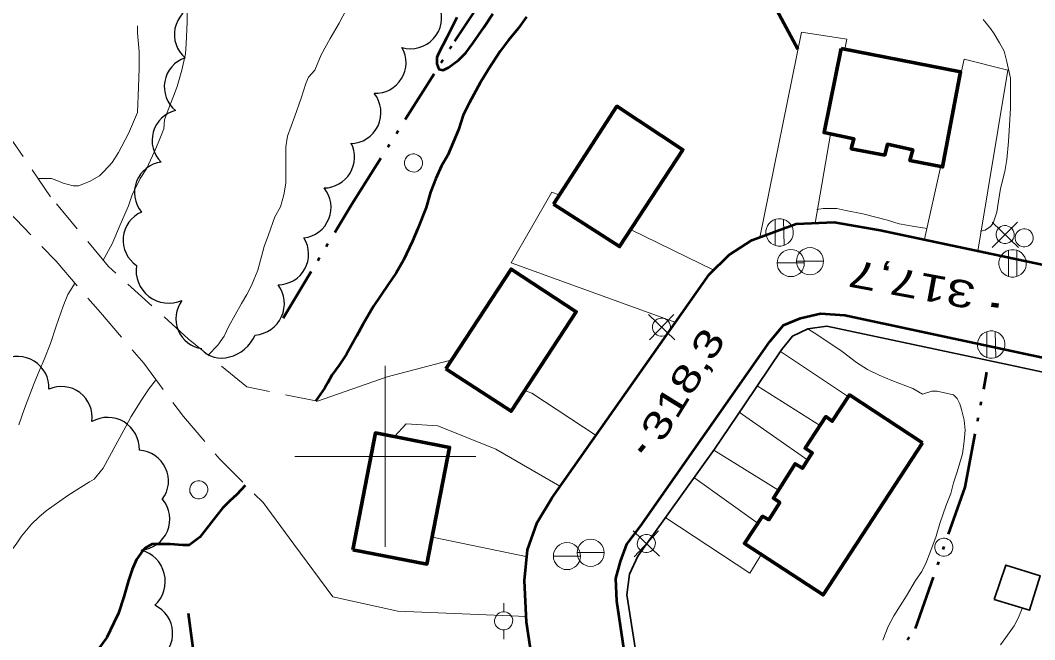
# Model space of a CAD drawing. Extents: x 240591 to 242335, y 5323482 to 5326937.
# Drawn here: x 241359.7 to 241471.8, y 5324579.8 to 5324648.2 of the extents above; entities that cross this region are included whole.
import ezdxf

# ---------------------------------------------------------------- set-up
doc = ezdxf.new("R2010")
doc.units = 0
doc.header["$LTSCALE"] = 1.2
for name, pattern in [('DASH_DOUBLE_DOT', [9.2, 5, -1.2, 0.3, -1.2, 0.3, -1.2]), ('LONG_DASHED', [7.5, 6, -1.5]), ('MEDIUM_DASHED', [4.5, 3, -1.5])]:
    doc.linetypes.add(name, pattern=pattern)
for name, color, linetype, lineweight in [('1', 7, 'Continuous', 53), ('19', 7, 'Continuous', 13), ('2', 7, 'Continuous', 13), ('21', 7, 'Continuous', 53), ('22', 7, 'LONG_DASHED', 70), ('3', 7, 'Continuous', 140), ('31', 7, 'Continuous', 70), ('36', 7, 'Continuous', 13), ('4', 7, 'DASH_DOUBLE_DOT', 53), ('44', 7, 'Continuous', 25), ('61', 7, 'Continuous', 13)]:
    doc.layers.add(name, color=color, linetype=linetype, lineweight=lineweight)

msp = doc.modelspace()

# ---------------------------------------------------------------- linework, layer by layer
at = {"layer": '1'}
for points in [[(241407.9, 5324648.5), (241406.8, 5324646.3), (241405.9, 5324644.6), (241405.7, 5324644.1), (241405.7, 5324643.4), (241405.9, 5324642.8), (241406.4, 5324642.7), (241407, 5324643), (241408.1, 5324643.8), (241408.9, 5324644.6), (241409.7, 5324645.7), (241410.9, 5324647.4), (241411.9, 5324648.9)], [(241415.6, 5324648.6), (241414.7, 5324647.3), (241413.6, 5324646), (241412.7, 5324644.8), (241411.4, 5324642.8), (241410.5, 5324641.3), (241409.3, 5324639.1), (241408.6, 5324637.7), (241408.1, 5324636.1), (241406.9, 5324633.3), (241406.2, 5324632.1), (241405.6, 5324630.7), (241405, 5324629.2), (241404.5, 5324627.5), (241403.6, 5324625.2), (241403, 5324623.8), (241402, 5324621.7), (241401.2, 5324620.3), (241400.3, 5324619), (241398.7, 5324616.6), (241397.5, 5324614.6), (241396.8, 5324613.3), (241395.7, 5324611.3), (241394.9, 5324610.1), (241394.1, 5324609), (241393.6, 5324608.1), (241393.3, 5324607.6), (241392.3, 5324606.1)], [(241384.5, 5324596.8), (241383.6, 5324595.8), (241382.8, 5324595.1), (241382, 5324594.3), (241381.3, 5324593.4), (241379.5, 5324591.1), (241378.3, 5324590.2), (241377.6, 5324590.2), (241376.2, 5324590.3), (241374.2, 5324590.3), (241373.5, 5324589.9), (241373.2, 5324589.6), (241372.5, 5324588.6), (241372, 5324587.5), (241371.6, 5324586.3), (241371.1, 5324584.5), (241370.5, 5324582.7), (241370, 5324581.6), (241369.2, 5324580), (241368.4, 5324578.9), (241368.1, 5324578.3), (241367.8, 5324578.1)]]:
    msp.add_lwpolyline(points, dxfattribs=at)
at = {"layer": '19'}
for p, q in [((241449.2, 5324635.6), (241447.5, 5324625.8)), ((241459.6, 5324624), (241461.4, 5324632.1)), ((241427.1, 5324625.1), (241436.3, 5324620.6)), ((241451.2, 5324606.6), (241443.7, 5324611.6)), ((241441.1, 5324607.8), (241448.1, 5324603.4)), ((241446.7, 5324599.6), (241439.1, 5324604.9)), ((241436.3, 5324600.7), (241443.4, 5324596.3)), ((241441.2, 5324592.6), (241434.2, 5324597.6)), ((241415.7, 5324588.9), (241405.2, 5324591.1))]:
    msp.add_line(p, q, dxfattribs=at)
at = {"layer": '19', "linetype": 'MEDIUM_DASHED'}
for points in [[(241392.5, 5324606.1), (241384.7, 5324607.7), (241378.2, 5324613), (241369.4, 5324621), (241363, 5324628.7), (241358.5, 5324635.3), (241354, 5324644.9), (241349.9, 5324657.2), (241346.1, 5324667.4), (241343.3, 5324672.7), (241341.3, 5324676.6)], [(241325.4, 5324637.6), (241334.6, 5324633.2), (241343.7, 5324632), (241351.5, 5324630), (241358.3, 5324627.1), (241363.6, 5324621.6), (241368.5, 5324615.9), (241373.3, 5324610.3), (241377.7, 5324604.4), (241381.7, 5324599.7), (241386.5, 5324594.9)]]:
    msp.add_lwpolyline(points, dxfattribs=at)
at = {"layer": '19'}
for points in [[(241441.4, 5324624.2), (241441.4, 5324624.2), (241446, 5324646.9), (241451, 5324646.1), (241450.8, 5324645)], [(241463.2, 5324640.4), (241464, 5324643.9), (241468.8, 5324642.7), (241465.5, 5324622.7)], [(241432.1, 5324614.8), (241413.9, 5324621.4), (241418.4, 5324629.2), (241419.2, 5324628.9)], [(241392.5, 5324606.1), (241400.2, 5324608.8), (241407.1, 5324610.6), (241407.3, 5324610.5)], [(241415.4, 5324607.3), (241416.2, 5324607), (241423.3, 5324602.3)], [(241401, 5324602.2), (241402.3, 5324603.6), (241405.8, 5324603.4), (241412.2, 5324600.8), (241419.3, 5324596.7)], [(241415.6, 5324582.3), (241401.4, 5324582.9), (241394.2, 5324584.5), (241389.9, 5324590.3), (241386.5, 5324594.9)], [(241431, 5324593.2), (241440.3, 5324587.1), (241441.6, 5324589.2)]]:
    msp.add_lwpolyline(points, dxfattribs=at)
at = {"layer": '2'}
for points in [[(241396.1, 5324650.2), (241394.9, 5324647.9), (241393.9, 5324646.2), (241392.9, 5324644.4), (241392.2, 5324642.7), (241392.2, 5324642.7)], [(241378.1, 5324649.3), (241378.1, 5324648), (241378, 5324645.6), (241377.9, 5324644.5), (241377.5, 5324642.7), (241377, 5324640.9), (241376.6, 5324639.8), (241376, 5324638.3), (241375.6, 5324637.2), (241375.5, 5324636.2), (241375, 5324634.9), (241374.5, 5324633.7), (241373.6, 5324631.8), (241372.9, 5324630.7), (241372, 5324628.9), (241371.6, 5324627.7), (241370.7, 5324625.6), (241369.8, 5324623.5), (241368.8, 5324621.7)], [(241372.6, 5324647.6), (241372.6, 5324646.8), (241372.8, 5324644.7), (241372.8, 5324642.9), (241372.7, 5324640.8), (241372.6, 5324638), (241372.4, 5324637.5), (241371.6, 5324635.7), (241370.5, 5324633.6), (241369.8, 5324632.5), (241368.9, 5324631.5), (241368.4, 5324631), (241367.3, 5324630.4), (241366.1, 5324629.9), (241365.5, 5324629.9), (241364.4, 5324630.2), (241363.7, 5324630.5), (241363.1, 5324630.7), (241361.6, 5324630.7)], [(241466.1, 5324648.3), (241466.9, 5324647.3), (241467.3, 5324646.7), (241467.9, 5324645.7), (241468.4, 5324644.8), (241468.7, 5324643.6), (241469.1, 5324641.8), (241469.1, 5324641.1), (241469.1, 5324638.5), (241469, 5324636.6), (241468.9, 5324634.8), (241468.7, 5324632.8), (241468.5, 5324631.5), (241468, 5324629.6), (241467.8, 5324628.2), (241467.6, 5324627), (241467.2, 5324625.8), (241466.9, 5324625.4), (241466.3, 5324625), (241465.8, 5324624.9)], [(241392.2, 5324642.7), (241391.5, 5324641.9), (241391.2, 5324641.2), (241390.7, 5324639.6), (241390, 5324637.6), (241389.2, 5324635.4), (241389, 5324634.2), (241389, 5324632.9), (241389, 5324630.2), (241388.8, 5324628.9), (241388.4, 5324627.6), (241387.8, 5324626.5), (241387.1, 5324624.5), (241386.6, 5324623.2), (241385.9, 5324620.6), (241385.2, 5324618.9), (241384.7, 5324617.9), (241384.1, 5324616.9), (241382.7, 5324614.4), (241382.2, 5324613.3), (241381.5, 5324612.3), (241380.4, 5324611.2)], [(241459.9, 5324625.2), (241458.5, 5324625.4), (241456.8, 5324625.7), (241455.5, 5324626.1), (241452.8, 5324626.8), (241450.9, 5324627.2), (241449.9, 5324627.4), (241448.4, 5324627.4), (241447.7, 5324627.3)], [(241365.7, 5324619.2), (241364.9, 5324617.9), (241364.4, 5324616.6), (241363.6, 5324614.4), (241363, 5324612.5), (241362.3, 5324610.7), (241361.8, 5324609.6), (241361.2, 5324608.1), (241360.1, 5324605.3), (241359.5, 5324603.5)], [(241446.7, 5324614.1), (241447.8, 5324613.4), (241450.5, 5324611.6), (241452.1, 5324610.4), (241453.3, 5324609.6), (241454.6, 5324609), (241456, 5324608.4), (241458.3, 5324607.5), (241459.4, 5324606.9)], [(241374.6, 5324608.4), (241373.9, 5324607.5), (241373.1, 5324606.3), (241371.9, 5324604.4), (241371.3, 5324603.3), (241370.2, 5324601.3), (241368.8, 5324598.7), (241367.8, 5324597.5), (241367.3, 5324597.2), (241364.9, 5324595.7), (241362.5, 5324594), (241361.7, 5324593.3), (241360.9, 5324592.5), (241359.8, 5324591.2), (241359.2, 5324590.3), (241358.5, 5324589.4), (241357.7, 5324588.6), (241356.9, 5324587.6), (241356.3, 5324587)], [(241459.4, 5324606.9), (241460.4, 5324607.2), (241461, 5324607.2), (241462.8, 5324606.8), (241463.2, 5324606.4), (241463.5, 5324605.8), (241463.7, 5324605.2), (241464, 5324604), (241464.1, 5324602.9), (241464, 5324601.7), (241463.8, 5324600.3), (241463.2, 5324598.3), (241462.8, 5324597.1), (241462.5, 5324595.9), (241462, 5324594.6), (241461.3, 5324592.6), (241460.9, 5324591.2), (241460.2, 5324589.3), (241459.8, 5324588.3), (241459.3, 5324587.3), (241458.6, 5324586.3), (241457.6, 5324584.6), (241456.2, 5324582.4), (241455.6, 5324581.2), (241455, 5324579.7)], [(241468, 5324579.2), (241468.6, 5324580), (241469.5, 5324581.3), (241470, 5324582.2), (241470.4, 5324583.2)]]:
    msp.add_lwpolyline(points, dxfattribs=at)
at = {"layer": '21'}
for points in [[(241422.3, 5324537.1), (241415.6, 5324581.7), (241415.4, 5324586.3), (241415.7, 5324589.7), (241416.8, 5324592.7), (241418.4, 5324595.4), (241435.8, 5324620.1), (241438, 5324622.3), (241440.5, 5324623.9), (241445.4, 5324625.7), (241449.6, 5324625.9), (241454.7, 5324625), (241487.7, 5324618)], [(241431, 5324547.6), (241425.6, 5324584), (241425.5, 5324586.5), (241426, 5324588.4), (241426.7, 5324590.3), (241428.2, 5324592.3), (241442.5, 5324612.7), (241444, 5324614.5), (241445.9, 5324615.3), (241448.1, 5324615.8), (241450.8, 5324615.6), (241475.6, 5324610.3), (241492, 5324606.6), (241494.5, 5324604.7), (241496, 5324602.3), (241496.6, 5324599.8), (241496.6, 5324597.7), (241496.2, 5324595.5), (241491.7, 5324574.9)]]:
    msp.add_lwpolyline(points, dxfattribs=at)
at = {"layer": '22'}
msp.add_lwpolyline([(241445.6, 5324645), (241437.9, 5324659.4), (241434.1, 5324666.7), (241428.8, 5324677.4), (241427.9, 5324678.7)], dxfattribs=at)
at = {"layer": '22', "linetype": 'Continuous', "lineweight": 35}
msp.add_lwpolyline([(241490.9, 5324577.6), (241495.3, 5324597.6), (241495, 5324600.1), (241493.7, 5324602.8), (241492.2, 5324604.5), (241488.6, 5324605.9), (241469.1, 5324610.1), (241448.8, 5324614.4), (241446.7, 5324614.1), (241445, 5324613.3), (241443.8, 5324611.8), (241439.7, 5324605.7), (241436.4, 5324600.8), (241427.9, 5324589), (241427, 5324587), (241426.7, 5324584.7), (241430.2, 5324562.5)], dxfattribs=at)
at = {"layer": '3'}
for p, q in [((241467, 5324616.8), (241467.8, 5324616.7)), ((241428.1, 5324600.6), (241428.6, 5324601.2))]:
    msp.add_line(p, q, dxfattribs=at)
at = {"layer": '31'}
for points in [[(241450.4, 5324645.1), (241463.6, 5324642.5), (241461.6, 5324632), (241458, 5324632.7), (241458.3, 5324633.9), (241455.5, 5324634.5), (241455.2, 5324633.3), (241451.5, 5324634), (241451.8, 5324635.1), (241448.5, 5324635.8)], [(241418.6, 5324627.9), (241425.6, 5324638.7), (241432.9, 5324633.9), (241425.9, 5324623.2)], [(241406.7, 5324609.7), (241413.9, 5324620.7), (241421.1, 5324616), (241413.9, 5324605)], [(241459.4, 5324601.5), (241448.4, 5324584.7), (241439.7, 5324590.4), (241441.7, 5324593.4), (241442.4, 5324593), (241443.6, 5324594.9), (241442.9, 5324595.4), (241445.3, 5324599.2), (241446.1, 5324598.7), (241447.2, 5324600.4), (241446.4, 5324600.9), (241448.7, 5324604.4), (241449.4, 5324603.9), (241451.3, 5324606.8)], [(241396.4, 5324589.7), (241398.9, 5324602.6), (241407.1, 5324601), (241404.6, 5324588.1)]]:
    msp.add_lwpolyline(points, close=True, dxfattribs=at)
at = {"layer": '31', "lineweight": 35}
msp.add_lwpolyline([(241467.3, 5324584.2), (241468.6, 5324588), (241472.4, 5324586.8), (241471.2, 5324583)], close=True, dxfattribs=at)
at = {"layer": '36'}
for p, q in [((241443.1, 5324626.2), (241443.1, 5324623.3)), ((241444.1, 5324623.3), (241444, 5324626.2)), ((241470, 5324623.1), (241467.1, 5324625.9)), ((241469.9, 5324625.9), (241467.1, 5324623.1)), ((241468.9, 5324622.8), (241468.9, 5324619.9)), ((241469.8, 5324619.9), (241469.8, 5324622.8)), ((241443.3, 5324621.4), (241446.3, 5324621.4)), ((241445.4, 5324621.6), (241448.4, 5324621.6)), ((241432, 5324612.9), (241429.1, 5324615.7)), ((241431.9, 5324615.7), (241429.2, 5324612.9)), ((241466.5, 5324613.8), (241466.5, 5324610.9)), ((241467.5, 5324610.9), (241467.4, 5324613.8)), ((241430.3, 5324589), (241427.4, 5324591.8)), ((241427.5, 5324588.9), (241430.2, 5324591.8)), ((241421.2, 5324589.4), (241424.2, 5324589.4)), ((241418.6, 5324589), (241421.6, 5324589)), ((241413.1, 5324583.8), (241413.1, 5324582.8)), ((241413.1, 5324579.8), (241413.1, 5324580.8))]:
    msp.add_line(p, q, dxfattribs=at)
for centre in [(241446.949, 5324621.582), (241444.819, 5324621.372), (241420.079, 5324588.992), (241422.699, 5324589.352)]:
    msp.add_circle(centre, 1.5, dxfattribs=at)
for centre, major_axis in [((241403.12, 5324632.433), (-0.463, 0.886)), ((241443.585, 5324624.757), (-0.703, 1.345)), ((241468.512, 5324624.515), (-0.463, 0.886)), ((241470.63, 5324624.153), (-0.463, 0.886)), ((241469.345, 5324621.337), (-0.703, 1.345)), ((241430.532, 5324614.285), (-0.463, 0.886)), ((241466.975, 5324612.367), (-0.703, 1.345)), ((241379.37, 5324596.323), (-0.463, 0.886)), ((241428.855, 5324590.378), (-0.463, 0.886)), ((241461.75, 5324589.963), (-0.463, 0.886)), ((241413.082, 5324581.829), (-0.463, 0.886))]:
    msp.add_ellipse(centre, major_axis=major_axis, ratio=0.999959, dxfattribs=at)
at = {"layer": '4'}
for points in [[(241388.7, 5324615.3), (241396.3, 5324627.9), (241407.7, 5324645.9), (241417.6, 5324661), (241424.4, 5324668.2), (241431.9, 5324666.9), (241446.2, 5324664), (241458.2, 5324661.9), (241462.7, 5324660.1), (241467.2, 5324660), (241470.1, 5324659.3)], [(241440.4, 5324545), (241440.4, 5324545), (241443.5, 5324557.3), (241452.4, 5324572.2), (241458.6, 5324581), (241464.1, 5324596.6), (241466.5, 5324609.3)], [(241378.2, 5324582.7), (241381.8, 5324555.7), (241386.5, 5324528), (241390.9, 5324504.7), (241393.9, 5324485.4), (241399.5, 5324484.2), (241421, 5324488.5), (241449.5, 5324493.5), (241473.3, 5324496.6), (241488.2, 5324498.8), (241492.7, 5324494.8), (241500.3, 5324485.3), (241513.1, 5324473.7), (241522.9, 5324463.6), (241532.4, 5324454.5), (241543.7, 5324443.4), (241553.7, 5324434.1), (241562.9, 5324425.2), (241571.5, 5324417.9), (241577.9, 5324414.3), (241580.3, 5324411.9), (241583.4, 5324409.6)]]:
    msp.add_lwpolyline(points, dxfattribs=at)
at = {"layer": '44'}
for centre, radius, start, end in [((241380.069, 5324646.629), 3.388, 107.49916, 229.31162), ((241398.903, 5324643.514), 3.386, 267.74854, 29.85974), ((241378.956, 5324640.853), 3.389, 108.87032, 230.7103), ((241377.606, 5324634.936), 3.389, 103.5832, 225.48247), ((241375.658, 5324629.159), 3.388, 97.26609, 219.3823), ((241385.357, 5324616.896), 3.487, 274.48534, 36.50236)]:
    msp.add_arc(centre, radius, start, end, dxfattribs=at)
for centre, major_axis, ratio, start_param, end_param in [((241402.869, 5324648.407), (2.42, 2.364), 0.980375, 3.6364937, 5.9045831), ((241396.181, 5324637.966), (1.273, 3.137), 0.984632, 3.5277491, 5.7877103), ((241393.26, 5324633.036), (1.595, 2.979), 0.982666, 3.6342197, 5.6862731), ((241390.595, 5324627.528), (2.99, -1.628), 0.999679, 5.3330293, 7.462279), ((241374.406, 5324623.907), (2.783, -1.936), 0.999983, 2.5932834, 4.7197069), ((241388.112, 5324622.371), (2.98, -1.68), 0.992049, 5.236243, 7.3505464), ((241376.079, 5324620.571), (-2.48, -2.651), 0.999638, 5.3152352, 7.4438142), ((241380.201, 5324615.238), (-0.885, -3.241), 0.995338, 4.3391719, 6.4044696), ((241382.461, 5324614.781), (2.174, 3.447), 0.843178, 2.9035264, 4.8450804), ((241359.359, 5324607.599), (2.95, 1.803), 0.996968, 5.6872704, 7.8072419), ((241364.144, 5324604.268), (2.06, 2.809), 0.983618, 5.2193969, 7.3213405), ((241369.265, 5324600.751), (1.83, 3.081), 0.986187, 5.2253035, 7.3268419), ((241372.607, 5324597.302), (-3.359, 0.701), 0.988984, 2.6993786, 4.8569503), ((241372.747, 5324593.078), (2.45, -2.406), 0.995788, 5.5605125, 7.7586118), ((241372.076, 5324586.178), (3.564, 0.532), 0.999633, 5.3172429, 7.4466725), ((241373.036, 5324580.434), (3.454, 0.205), 0.999732, 5.2221095, 7.3450171)]:
    msp.add_ellipse(centre, major_axis=major_axis, ratio=ratio, start_param=start_param, end_param=end_param, dxfattribs=at)
at = {"layer": '61'}
for points in [[(241400, 5324610), (241400, 5324600), (241400, 5324590)], [(241390, 5324600), (241400, 5324600), (241410, 5324600)]]:
    msp.add_lwpolyline(points, dxfattribs=at)

# ---------------------------------------------------------------- texts
at = {"layer": '3'}
for s, rotation, width, p in [('317,7', 169.526, 1.4, (241465.4, 5324619.2)), ('318,3', 58.314, 1.35, (241430.6, 5324601.4))]:
    msp.add_text(s, height=3, rotation=rotation, dxfattribs=dict(at, width=width)).set_placement(p)

doc.saveas('drawing.dxf')
